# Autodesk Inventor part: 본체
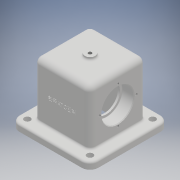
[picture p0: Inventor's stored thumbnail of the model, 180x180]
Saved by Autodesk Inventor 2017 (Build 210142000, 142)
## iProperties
Part Number: 본체
Material: 일반
Document SubType Name: Modeling
Designer: MRC
Density: 1 g/cm^3
Appearance: 기본값
Author: MRC
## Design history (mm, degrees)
sketch "스케치2"
  geometry: L1 (-58, 58)-(58, 58); L2 (58, 58)-(58, -58); L3 (58, -58)-(-58, -58); L4 (-58, -58)-(-58, 58); L5 (-58, 58)-(58, -58); L6 (58, 58)-(-58, -58); 1 further point
  constraints: 12 end point, 2 midpoint, 2 parallel, 1 horizontal, 1 perpendicular
  dimensions: "d2" = 116 distance of L2.end L3.end; "d3" = 116 distance of L1.end L2.end
extrude "돌출1" new body sketch "스케치2" distance "d4" = 10; taper "d5" = 0 deg
sketch "스케치3"
  geometry: L1 (-41, 41)-(41, 41); L2 (41, 41)-(41, -41); L3 (41, -41)-(-41, -41); L4 (-41, -41)-(-41, 41); L5 (-41, 41)-(41, -41); L6 (41, 41)-(-41, -41); 1 further point
  constraints: 12 end point, 2 midpoint, 2 parallel, 1 horizontal, 1 perpendicular
  dimensions: "d6" = 82 distance of L1.start L1.end; "d7" = 82 distance of L1.end L2.end
extrude "돌출2" join sketch "스케치3" distance "d8" = 80; taper "d9" = 0 deg
fillet "모깎기1" dims "d10" = 12
sketch "스케치4"
  geometry: L1 (10, 87)-(10, -5) reference; 4 further points
  constraints: 2 midpoint, 1 horizontal alignment
  dimensions: "d13" = 48 distance of point (10, 41) point (-38, 41)
hole "구멍1" sketch "스케치4" at (-38, 41) diameter "d14" = 40; stored, may be unused: countersink angle "d18" = 90 deg, drill point angle "d20" = 118 deg; dims "d15" = 6, "d16" = 47, "d17" = 17, "d19" = 8
sketch "스케치5"
  geometry: L1 (10, 87)-(10, -5) reference; C1 r 20 at (-38, 41) reference; 3 further points
  constraints: 1 horizontal alignment, 1 midpoint
  dimensions: "d21" = 27 distance of C1.centre point (-65, 41)
hole "구멍2" sketch "스케치5" at (-65, 41) diameter "d22" = 3.242; stored, may be unused: countersink angle "d26" = 90 deg, drill point angle "d28" = 118 deg; dims "d23" = 8, "d24" = 47, "d25" = 17, "d27" = 10
chamfer "모따기1" distance "d32" = 1; stored, may be unused: second distance "d33" = 2, angle "d34" = 45 deg
chamfer "모따기2" distance "d35" = 1; stored, may be unused: second distance "d36" = 2, angle "d37" = 45 deg
sketch "스케치6"
  geometry: L1 (-21, 30)-(21, 30); L2 (21, 30)-(21, -30); L3 (21, -30)-(-21, -30); L4 (-21, -30)-(-21, 30); L5 (-21, 30)-(21, -30); L6 (21, 30)-(-21, -30); 1 further point
  constraints: 12 end point, 2 midpoint, 2 parallel, 1 horizontal, 1 perpendicular
  dimensions: "d38" = 42 distance of L1.start L1.end; "d39" = 60 distance of L1.end L2.end
extrude "돌출3" cut sketch "스케치6" distance "d40" = 80; taper "d41" = 0 deg
sketch "스케치7"
  geometry: C1 r 7.5 at (0, 0); 1 further point
  constraints: 1 centre point, 1 coincident
  dimensions: "d42" = 15 diameter of C1
extrude "돌출4" join sketch "스케치7" distance "d43" = 4; taper "d44" = 0 deg
sketch "스케치8"
  geometry: C1 r 7.5 at (0, 0) reference; 2 further points
  constraints: 1 coincident
hole "구멍3" sketch "스케치8" at (0, 0) diameter "d45" = 4.917; stored, may be unused: countersink angle "d49" = 90 deg, drill point angle "d51" = 118 deg; dims "d46" = 12, "d47" = 47, "d48" = 17, "d50" = 17.1
fillet "모깎기2" dims "d52" = 3
fillet "모깎기3" dims "d53" = 8
fillet "모깎기4" dims "d54" = 8
fillet "모깎기5" dims "d55" = 3
fillet "모깎기6" dims "d56" = 3
fillet "모깎기7" dims "d57" = 3
sketch "스케치9"
  geometry: A1 r 9 centre (46, 46) between (55, 46) and (46, 55) reference; 2 further points
  constraints: 1 coincident
hole "구멍4" sketch "스케치9" at (46, 46) diameter "d58" = 9; stored, may be unused: countersink angle "d62" = 90 deg, drill point angle "d64" = 118 deg; dims "d59" = 6, "d60" = 4, "d61" = 2, "d63" = 8
fillet "모깎기8" dims "d65" = 0.6
sketch "스케치10"
  geometry: L1 (79, -82)-(-13, -82) reference; 3 further points
  constraints: 1 midpoint, 1 vertical alignment, 1 other
  dimensions: "d66" = 48 distance from line of L1 point (33, -34)
feature "엠보싱1" sketch "스케치10" dims "d2" = 116, "d3" = 116, "d67" = 0.5, "d68" = 0
node "솔리드1"
pattern_circular "원형 패턴1" dims angle "d30" = 360 deg
mirror "미러1"
mirror "미러2"
mirror "미러3"
